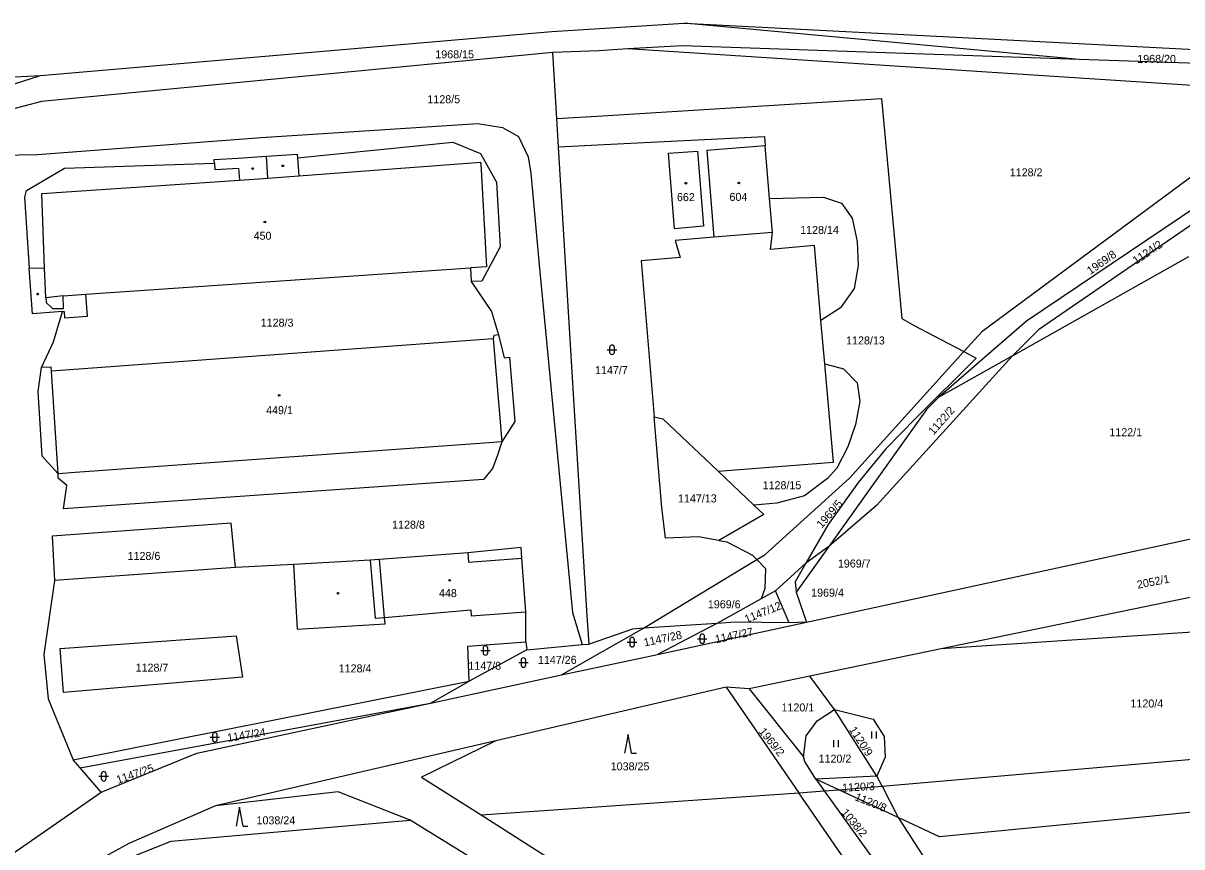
# Model space of a CAD drawing. Extents: x -793666 to -785424, y -1118958 to -1108761.
# Drawn here: x -787061.6 to -786815.6, y -1115772 to -1115597.1 of the extents above; entities that cross this region are included whole.
import ezdxf

# ---------------------------------------------------------------- set-up
doc = ezdxf.new("R2010")
doc.units = 0
for name, color, linetype in [('Hranice parcel', 7, 'Continuous'), ('Parcelní čísla', 7, 'Continuous'), ('Vnitřní kresba', 7, 'Continuous'), ('Značky budov', 7, 'Continuous'), ('Značky kultur', 7, 'Continuous')]:
    doc.layers.add(name, color=color, linetype=linetype)

msp = doc.modelspace()

# ---------------------------------------------------------------- linework, layer by layer
at = {"layer": 'Hranice parcel'}
for p, q in [((-786921.27, -1115597.08), (-786796.1, -1115603.54)), ((-786837.35, -1115604.8), (-786921.27, -1115597.08)), ((-786948.3, -1115617.34), (-786949.16, -1115603.3)), ((-786789.48, -1115611.9), (-786933.2, -1115602.56)), ((-786790.33, -1115606.42), (-786837.35, -1115604.8)), ((-787094.74, -1115619.88), (-787057.9, -1115608.19)), ((-786947.93, -1115623.34), (-786948.3, -1115617.34)), ((-786903.11, -1115634.3), (-786904.03, -1115623.11)), ((-786851.55, -1115667.72), (-786814.08, -1115646.63)), ((-786891.4, -1115669.38), (-786892.23, -1115660.23)), ((-786851.55, -1115667.72), (-786867.17, -1115676.51)), ((-786914.05, -1115692.2), (-786906.43, -1115699.44)), ((-786895.26, -1115724.29), (-786789.2, -1115701.2)), ((-786890.56, -1115708.2), (-786897.46, -1115717.88)), ((-786890.56, -1115708.2), (-786895.41, -1115711.76)), ((-786759.56, -1115707.76), (-786866.69, -1115729.95)), ((-787004.21, -1115711.99), (-787016.54, -1115712.67)), ((-786929.88, -1115725.56), (-786905.82, -1115710.97)), ((-786895.41, -1115711.76), (-786901.83, -1115717.58)), ((-786895.41, -1115711.76), (-786897.68, -1115715.7)), ((-787016.54, -1115712.67), (-787054.92, -1115715.4)), ((-786897.68, -1115715.7), (-786897.46, -1115717.88)), ((-786904.9, -1115719.28), (-786914.34, -1115724.54)), ((-786901.83, -1115717.58), (-786904.9, -1115719.28)), ((-786898.95, -1115724.41), (-786901.83, -1115717.58)), ((-786897.46, -1115717.88), (-786895.26, -1115724.29)), ((-786954.84, -1115728.4), (-786954.86, -1115722.07)), ((-786941.44, -1115728.96), (-786941.81, -1115722.93)), ((-786914.34, -1115724.54), (-786929.88, -1115725.56)), ((-786926.92, -1115731.09), (-786895.26, -1115724.29)), ((-786914.34, -1115724.54), (-786926.92, -1115731.09)), ((-786895.26, -1115724.29), (-786898.95, -1115724.41)), ((-786757.99, -1115722.68), (-786866.69, -1115729.95)), ((-786947.31, -1115735.47), (-786929.88, -1115725.56)), ((-786954.84, -1115728.4), (-786954.66, -1115730.12)), ((-786954.66, -1115730.12), (-786942.94, -1115729.01)), ((-786942.94, -1115729.01), (-786941.44, -1115728.96)), ((-786954.66, -1115730.12), (-786966.93, -1115736.79)), ((-786947.31, -1115735.47), (-786926.92, -1115731.09)), ((-786866.69, -1115729.95), (-786894.58, -1115735.73)), ((-787050.96, -1115753.47), (-786966.93, -1115736.79)), ((-786975.1, -1115741.44), (-786947.31, -1115735.47)), ((-786975.1, -1115741.44), (-786966.93, -1115736.79)), ((-786894.58, -1115735.73), (-786907.45, -1115738.4)), ((-786889.32, -1115742.8), (-786894.58, -1115735.73)), ((-786912.35, -1115738.07), (-786961.23, -1115749.44)), ((-786907.45, -1115738.4), (-786912.35, -1115738.07)), ((-786912.35, -1115738.07), (-786896.92, -1115760.48)), ((-786907.45, -1115738.4), (-786895.9, -1115752.83)), ((-787049.52, -1115755.15), (-786975.1, -1115741.44)), ((-786880.32, -1115756.93), (-786889.32, -1115742.8)), ((-786961.23, -1115749.44), (-787020.77, -1115763.28)), ((-786879.23, -1115759.05), (-786754.91, -1115748.31)), ((-787049.52, -1115755.15), (-787050.96, -1115753.47)), ((-787045, -1115760.38), (-787049.52, -1115755.15)), ((-786880.32, -1115756.93), (-786893.29, -1115757.58)), ((-786893.29, -1115757.58), (-786891.5, -1115760.08)), ((-786888.43, -1115759.85), (-786893.29, -1115757.58)), ((-786888.43, -1115759.85), (-786879.23, -1115759.05)), ((-786879.23, -1115759.05), (-786880.32, -1115756.93)), ((-786879.23, -1115759.05), (-786875.79, -1115765.76)), ((-786964.37, -1115765.14), (-786896.92, -1115760.48)), ((-786896.92, -1115760.48), (-786891.5, -1115760.08)), ((-786891.5, -1115760.08), (-786888.43, -1115759.85)), ((-786875.79, -1115765.76), (-786888.43, -1115759.85)), ((-786875.79, -1115765.76), (-786858.38, -1115792.69))]:
    msp.add_line(p, q, dxfattribs=at)
for points in [[(-787057.9, -1115608.19), (-786949.33, -1115598.82), (-786921.27, -1115597.08)], [(-786837.35, -1115604.8), (-786921.63, -1115601.89), (-786933.2, -1115602.56)], [(-786949.16, -1115603.3), (-787057.73, -1115613.73), (-787072.76, -1115617.7)], [(-786933.2, -1115602.56), (-786939.38, -1115602.92), (-786949.16, -1115603.3)], [(-787162.28, -1115638.4), (-787156.55, -1115624.72), (-787138.27, -1115619.76), (-787112.14, -1115614.55), (-787072.9, -1115608.98), (-787057.9, -1115608.19)], [(-786948.3, -1115617.34), (-786938.58, -1115616.74), (-786907.97, -1115614.85), (-786879.32, -1115613.08), (-786875.03, -1115659.76), (-786872.57, -1115661.19), (-786868.24, -1115663.46), (-786861.87, -1115666.81)], [(-786789.48, -1115611.9), (-786858.06, -1115662.6), (-786861.87, -1115666.81)], [(-787098.07, -1115625.7), (-787058.53, -1115624.94), (-787011.08, -1115621.37), (-786965.09, -1115618.39), (-786959.82, -1115619.25), (-786956.42, -1115621.12), (-786954.38, -1115625.47), (-786953.83, -1115628.93), (-786952.03, -1115648.41), (-786944.93, -1115722.22), (-786942.94, -1115729.01)], [(-786947.93, -1115623.34), (-786938.22, -1115622.85), (-786904.18, -1115621.14), (-786904.03, -1115623.11)], [(-787003.34, -1115625.66), (-786970.39, -1115622.33), (-786964.51, -1115624.76), (-786961.07, -1115630.85), (-786960.32, -1115644.56), (-786964.24, -1115651.84), (-786966.48, -1115651.95)], [(-786941.81, -1115722.93), (-786944.64, -1115676.95), (-786947.93, -1115623.34)], [(-786904.03, -1115623.11), (-786916.44, -1115624.09), (-786914.98, -1115642.53), (-786923.14, -1115643.19), (-786922.09, -1115646.8), (-786930.41, -1115647.53), (-786927.59, -1115680.64)], [(-786795.06, -1115623.32), (-786804.85, -1115630.88), (-786848.57, -1115660.33), (-786867.17, -1115676.51)], [(-787020.98, -1115626.78), (-787021.04, -1115626), (-787016.01, -1115625.72), (-787009.94, -1115625.31), (-787003.39, -1115624.86), (-787003.34, -1115625.66)], [(-786924.56, -1115624.71), (-786918.39, -1115624.22), (-786917.12, -1115640.21), (-786923.27, -1115640.75), (-786924.56, -1115624.71)], [(-787060.25, -1115649.08), (-787061.22, -1115633.99), (-787060.89, -1115632.64), (-787052.85, -1115627.89), (-787020.98, -1115626.78)], [(-786794.77, -1115627.05), (-786846.02, -1115662.21), (-786851.55, -1115667.72)], [(-786903.11, -1115634.3), (-786891.68, -1115634.02), (-786887.82, -1115635.26), (-786885.61, -1115638.49), (-786884.52, -1115643.44), (-786884.3, -1115648.5), (-786885.17, -1115653.44), (-786888.09, -1115657.5), (-786892.23, -1115660.23)], [(-786892.23, -1115660.23), (-786893.59, -1115644.31), (-786902.94, -1115645.13), (-786902.51, -1115641.51), (-786903.11, -1115634.3)], [(-787053.23, -1115658.32), (-787059.63, -1115658.76), (-787060.29, -1115649.08), (-787060.25, -1115649.08)], [(-787048.28, -1115654.61), (-786966.61, -1115648.99), (-786966.48, -1115651.95)], [(-786966.48, -1115651.95), (-786962.17, -1115658.27), (-786960.66, -1115663.26)], [(-787053.23, -1115658.32), (-787052.88, -1115658.29), (-787052.79, -1115659.65), (-787047.95, -1115659.32), (-787048.28, -1115654.61)], [(-787057.73, -1115670.22), (-787055.17, -1115664.75), (-787053.23, -1115658.32)], [(-786960.66, -1115663.26), (-786959.45, -1115668.1), (-786958.31, -1115667.99), (-786957.17, -1115681.66), (-786959.97, -1115685.99), (-786960.96, -1115689.01), (-786961.94, -1115691.66), (-786963.85, -1115694), (-787053.01, -1115700.22), (-787052.34, -1115695.25), (-787054.15, -1115693.65), (-787054.2, -1115692.78), (-787057.54, -1115688.99), (-787058.4, -1115675.3), (-787057.73, -1115670.22)], [(-786960.66, -1115663.26), (-786961.68, -1115663.37), (-786961.8, -1115664.09), (-787055.58, -1115670.93), (-787055.63, -1115670.09), (-787057.73, -1115670.22)], [(-786905.82, -1115710.97), (-786904.05, -1115709.89), (-786886.17, -1115693.68), (-786861.87, -1115666.81)], [(-786861.87, -1115666.81), (-786859.28, -1115668.17), (-786872.07, -1115680.95), (-786878.42, -1115687.48), (-786884.22, -1115694.51), (-786890.64, -1115703.51), (-786895.41, -1115711.76)], [(-786851.55, -1115667.72), (-786880.38, -1115699.46), (-786890.56, -1115708.2)], [(-786914.05, -1115692.2), (-786889.57, -1115690.27), (-786891.4, -1115669.38)], [(-786891.4, -1115669.38), (-786887.39, -1115670.5), (-786884.52, -1115673.42), (-786883.95, -1115677.4), (-786884.88, -1115682.3), (-786886.47, -1115687.06), (-786888.82, -1115691.56), (-786890.81, -1115693.78), (-786895.68, -1115697.4), (-786901.56, -1115698.98), (-786906.43, -1115699.44)], [(-786867.17, -1115676.51), (-786869.79, -1115679.07), (-786890.56, -1115708.2)], [(-786913.91, -1115706.9), (-786918.17, -1115706.14), (-786925.21, -1115706.39), (-786925.96, -1115699.88), (-786927.59, -1115680.64)], [(-786927.59, -1115680.64), (-786925.77, -1115681.06), (-786914.05, -1115692.2)], [(-786906.43, -1115699.44), (-786904.36, -1115701.41), (-786913.91, -1115706.9)], [(-787016.54, -1115712.67), (-787017.4, -1115703.27), (-787055.41, -1115705.97), (-787054.92, -1115715.4)], [(-786913.91, -1115706.9), (-786912.16, -1115707.21), (-786906.76, -1115710), (-786905.82, -1115710.97)], [(-786954.86, -1115722.07), (-786955.74, -1115710.7), (-786955.87, -1115708.43), (-786967.2, -1115709.57), (-786985.92, -1115710.95), (-786987.91, -1115711.09), (-787004.21, -1115711.99)], [(-787004.21, -1115711.99), (-787003.45, -1115725.74), (-786984.76, -1115724.63), (-786984.88, -1115723.23), (-786966.54, -1115721.64), (-786966.44, -1115722.93), (-786954.86, -1115722.07)], [(-786905.82, -1115710.97), (-786903.99, -1115712.84), (-786904.1, -1115717.14), (-786904.9, -1115719.28)], [(-787054.92, -1115715.4), (-787057.19, -1115731.12), (-787056.28, -1115740.53), (-787050.96, -1115753.47)], [(-786898.95, -1115724.41), (-786910.41, -1115724.28), (-786914.34, -1115724.54)], [(-787015.05, -1115735.92), (-787053.06, -1115739.2), (-787053.75, -1115729.82), (-787016.4, -1115727.19), (-787015.05, -1115735.92)], [(-786929.88, -1115725.56), (-786932.25, -1115725.73), (-786941.44, -1115728.96)], [(-786966.93, -1115736.79), (-786967.18, -1115729.33), (-786954.84, -1115728.4)], [(-787045, -1115760.38), (-787024.73, -1115752.1), (-786975.1, -1115741.44)], [(-786895.9, -1115752.83), (-786895.31, -1115748.42), (-786893.03, -1115745.2), (-786889.32, -1115742.8)], [(-786889.32, -1115742.8), (-786881.14, -1115744.83), (-786878.77, -1115748.55), (-786878.55, -1115752.91), (-786880.32, -1115756.93)], [(-786961.23, -1115749.44), (-786977.04, -1115757.17), (-786964.37, -1115765.14)], [(-786893.29, -1115757.58), (-786895.63, -1115753.86), (-786895.9, -1115752.83)], [(-786712.15, -1115754.3), (-786741.91, -1115757.42), (-786821.8, -1115765.46), (-786867.05, -1115769.85), (-786875.79, -1115765.76)], [(-787071.85, -1115779.08), (-787064.93, -1115774.13), (-787045, -1115760.38)], [(-786979.45, -1115766.29), (-786994.74, -1115760.25), (-787020.77, -1115763.28)], [(-786831.78, -1115835.92), (-786838.58, -1115834.07), (-786850.97, -1115827.21), (-786896.92, -1115760.48)], [(-786891.5, -1115760.08), (-786847.84, -1115820.86), (-786835.82, -1115828.99)], [(-787020.77, -1115763.28), (-787039.17, -1115771.28), (-787059.63, -1115782.48)], [(-787059.63, -1115782.48), (-787030.16, -1115770.72), (-786979.45, -1115766.29)], [(-786818.52, -1115859.15), (-786824.82, -1115858.48), (-786892.84, -1115819.73), (-786979.45, -1115766.29)], [(-786964.37, -1115765.14), (-786891.74, -1115811.54), (-786822.51, -1115851.81)]]:
    msp.add_lwpolyline(points, dxfattribs=at)
at = {"layer": 'Vnitřní kresba'}
for p, q in [((-787009.62, -1115629.97), (-787009.94, -1115625.31)), ((-787003.34, -1115625.66), (-787003.07, -1115629.52)), ((-787020.98, -1115626.78), (-787020.89, -1115628.14)), ((-787020.89, -1115628.14), (-787015.86, -1115627.87)), ((-787015.86, -1115627.87), (-787015.69, -1115630.39)), ((-787003.07, -1115629.52), (-786964.44, -1115626.58)), ((-786964.42, -1115626.88), (-786964.44, -1115626.58)), ((-786964.42, -1115626.88), (-786963.21, -1115648.8)), ((-787057.66, -1115633.26), (-787015.69, -1115630.39)), ((-787015.69, -1115630.39), (-787009.62, -1115629.97)), ((-787009.62, -1115629.97), (-787003.07, -1115629.52)), ((-787057.04, -1115649.06), (-787057.66, -1115633.26)), ((-786902.51, -1115641.51), (-786914.98, -1115642.53)), ((-787060.25, -1115649.08), (-787057.04, -1115649.06)), ((-787056.79, -1115655.37), (-787057.04, -1115649.06)), ((-786963.21, -1115648.8), (-786966.61, -1115648.99)), ((-787053.1, -1115654.94), (-787056.79, -1115655.37)), ((-787056.79, -1115655.37), (-787056.7, -1115656.39)), ((-787053.1, -1115654.94), (-787048.28, -1115654.61)), ((-787053.03, -1115657.64), (-787053.1, -1115654.94)), ((-787056.7, -1115656.39), (-787055.39, -1115657.69)), ((-787055.39, -1115657.69), (-787053.03, -1115657.64)), ((-786961.8, -1115664.09), (-786959.97, -1115685.99)), ((-787054.2, -1115692.78), (-787055.58, -1115670.93)), ((-786963.64, -1115686.25), (-787050.58, -1115692.49)), ((-786959.97, -1115685.99), (-786963.64, -1115686.25)), ((-787050.58, -1115692.49), (-787054.2, -1115692.78)), ((-786967.2, -1115709.57), (-786967.05, -1115711.51)), ((-786987.91, -1115711.09), (-786986.88, -1115723.4)), ((-786984.88, -1115723.23), (-786985.92, -1115710.95)), ((-786967.05, -1115711.51), (-786955.74, -1115710.7)), ((-786986.88, -1115723.4), (-786984.88, -1115723.23))]:
    msp.add_line(p, q, dxfattribs=at)
at = {"layer": 'Značky budov'}
for centre in [(-787012.88, -1115627.94), (-787006.45, -1115627.37), (-786920.88, -1115631.06), (-786909.65, -1115631.02), (-787010.28, -1115639.29), (-787058.53, -1115654.61), (-787007.24, -1115676.08), (-786971.03, -1115715.37), (-786994.76, -1115718.11)]:
    msp.add_circle(centre, 0.175, dxfattribs=at)
at = {"layer": 'Značky kultur'}
for p, q in [((-786937.57, -1115666.42), (-786935.57, -1115666.42)), ((-786937.07, -1115665.92), (-786937.07, -1115666.92)), ((-786936.07, -1115666.92), (-786936.07, -1115665.92)), ((-786917.91, -1115727.27), (-786917.91, -1115728.27)), ((-786916.91, -1115728.27), (-786916.91, -1115727.27)), ((-786963.94, -1115729.75), (-786963.94, -1115730.75)), ((-786962.94, -1115730.75), (-786962.94, -1115729.75)), ((-786933.32, -1115728.5), (-786931.32, -1115728.5)), ((-786932.82, -1115728), (-786932.82, -1115729)), ((-786931.82, -1115729), (-786931.82, -1115728)), ((-786918.41, -1115727.77), (-786916.41, -1115727.77)), ((-786964.44, -1115730.25), (-786962.44, -1115730.25)), ((-786956.38, -1115732.84), (-786954.38, -1115732.84)), ((-786955.88, -1115732.34), (-786955.88, -1115733.34)), ((-786954.88, -1115733.34), (-786954.88, -1115732.34)), ((-787021.88, -1115748.68), (-787019.88, -1115748.68)), ((-787021.38, -1115748.18), (-787021.38, -1115749.18)), ((-787020.38, -1115749.18), (-787020.38, -1115748.18)), ((-786933.15, -1115748.08), (-786933.9, -1115752.08)), ((-786932.4, -1115752.08), (-786933.15, -1115748.08)), ((-786889.45, -1115750.82), (-786889.45, -1115749.32)), ((-786888.45, -1115750.82), (-786888.45, -1115749.32)), ((-786881.4, -1115748.99), (-786881.4, -1115747.49)), ((-786880.4, -1115748.99), (-786880.4, -1115747.49)), ((-786932.4, -1115752.08), (-786931.4, -1115752.08)), ((-787045, -1115756.48), (-787045, -1115757.48)), ((-787044, -1115757.48), (-787044, -1115756.48)), ((-787045.5, -1115756.98), (-787043.5, -1115756.98)), ((-787015.64, -1115763.56), (-787016.39, -1115767.56)), ((-787014.89, -1115767.56), (-787015.64, -1115763.56)), ((-787014.89, -1115767.56), (-787013.89, -1115767.56))]:
    msp.add_line(p, q, dxfattribs=at)
for centre, start, end in [((-786936.57, -1115665.92), 0, 180), ((-786936.57, -1115666.92), 180, 359.9879), ((-786917.41, -1115727.27), 0, 180), ((-786963.44, -1115729.75), 0, 180), ((-786932.32, -1115728), 0, 180), ((-786932.32, -1115729), 180, 359.9879), ((-786917.41, -1115728.27), 180, 359.9879), ((-786963.44, -1115730.75), 180, 359.9879), ((-786955.38, -1115732.34), 0, 180), ((-786955.38, -1115733.34), 180, 359.9879), ((-787020.88, -1115748.18), 0, 180), ((-787020.88, -1115749.18), 180, 359.9879), ((-787044.5, -1115756.48), 0, 180), ((-787044.5, -1115757.48), 180, 359.9879)]:
    msp.add_arc(centre, 0.5, start, end, dxfattribs=at)

# ---------------------------------------------------------------- texts
at = {"layer": 'Parcelní čísla'}
for s, p in [('1968/15', (-786974.09, -1115604.54)), ('1968/20', (-786825.05, -1115605.51)), ('1128/5', (-786975.77, -1115614.08)), ('1128/2', (-786852.12, -1115629.6)), ('662', (-786922.78, -1115634.87)), ('604', (-786911.63, -1115634.82)), ('1128/14', (-786896.62, -1115641.83)), ('450', (-787012.67, -1115643.06)), ('1128/3', (-787011.16, -1115661.52)), ('1128/13', (-786886.87, -1115665.29)), ('1147/7', (-786940.17, -1115671.59)), ('449/1', (-787010.01, -1115680.08)), ('1122/1', (-786830.97, -1115684.78)), ('1128/15', (-786904.59, -1115696.03)), ('1147/13', (-786922.56, -1115698.83)), ('1128/8', (-786983.26, -1115704.41)), ('1128/6', (-787039.42, -1115711.04)), ('1969/7', (-786888.61, -1115712.66)), ('448', (-786973.31, -1115718.93)), ('1969/4', (-786894.29, -1115718.84)), ('1969/6', (-786916.22, -1115721.31)), ('1147/26', (-786952.3, -1115733.11)), ('1128/7', (-787037.72, -1115734.76)), ('1128/4', (-786994.6, -1115734.92)), ('1147/8', (-786967.07, -1115734.37)), ('1120/1', (-786900.58, -1115743.21)), ('1120/4', (-786826.49, -1115742.37)), ('1038/25', (-786936.84, -1115755.72)), ('1120/2', (-786892.71, -1115754.09)), ('1038/24', (-787012.05, -1115767.18))]:
    msp.add_text(s, height=1.7, dxfattribs=at).set_placement(p)
for s, rotation, p in [('1124/2', 34, (-786825.29, -1115648.37)), ('1969/8', 35, (-786834.99, -1115650.55)), ('1122/2', 49, (-786868.27, -1115684.63)), ('1969/5', 49, (-786892.04, -1115704.43)), ('2052/1', 11, (-786824.92, -1115717.16)), ('1147/12', 22, (-786908.02, -1115724.48)), ('1147/28', 12, (-786929.64, -1115729.43)), ('1147/27', 12, (-786914.5, -1115728.75)), ('1147/24', 9, (-787018.13, -1115749.67)), ('1969/2', 309, (-786905.49, -1115747.52)), ('1120/9', 303, (-786886.28, -1115747.09)), ('1147/25', 19, (-787041.46, -1115758.6)), ('1120/3', 3, (-786887.66, -1115760.25)), ('1120/8', 338, (-786885.15, -1115762)), ('1038/2', 310, (-786887.99, -1115764.74))]:
    msp.add_text(s, height=1.7, rotation=rotation, dxfattribs=at).set_placement(p)

doc.saveas('drawing.dxf')
